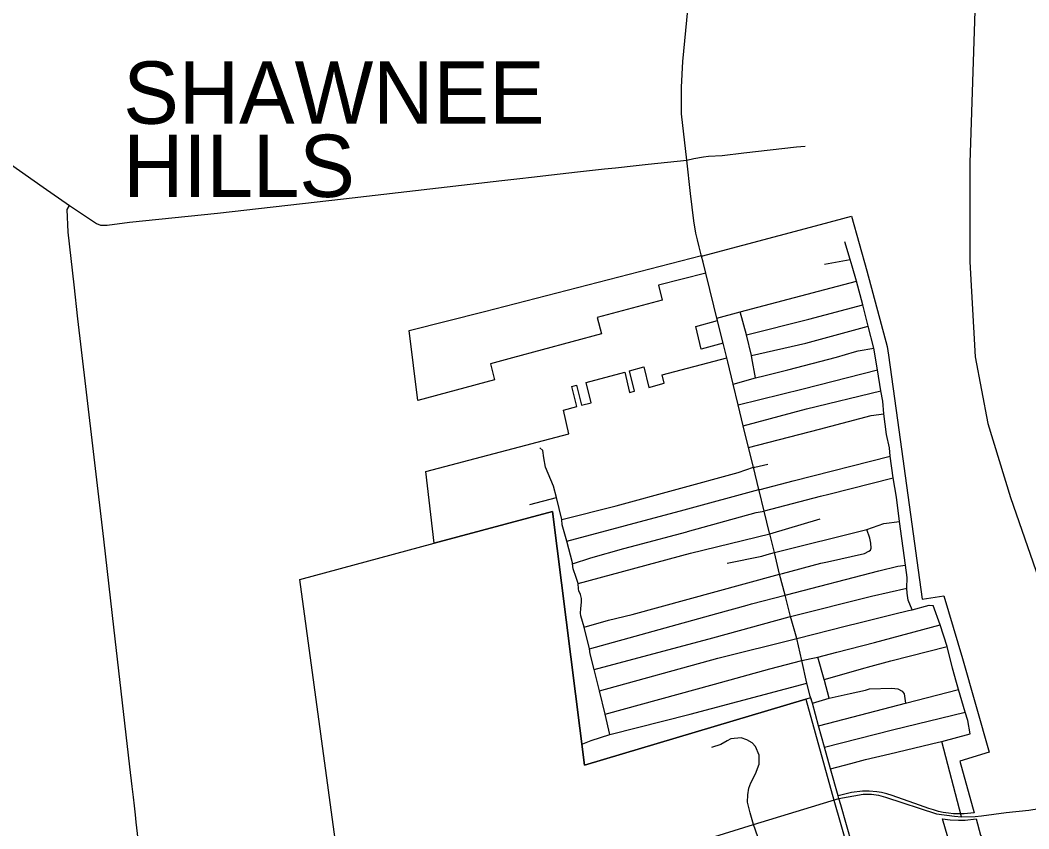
# Model space of a CAD drawing. Extents: x 1729596 to 1925846, y 659247 to 911751.
# Drawn here: x 1785084 to 1793175, y 784970 to 791458 of the extents above; entities that cross this region are included whole.
import ezdxf

# ---------------------------------------------------------------- set-up
doc = ezdxf.new("R2010")
doc.units = 0
for name, color, linetype in [('GM_X_City_Street', 7, 'Continuous'), ('GM_X_Corporation', 7, 'Continuous'), ('GM_X_Corporation_Text', 7, 'Continuous'), ('GM_X_County_Road', 7, 'Continuous'), ('GM_X_State_Route', 7, 'Continuous'), ('GM_X_Township', 7, 'Continuous'), ('GM_X_Township_Road', 7, 'Continuous')]:
    doc.layers.add(name, color=color, linetype=linetype)

msp = doc.modelspace()

# ---------------------------------------------------------------- linework, layer by layer
at = {"layer": 'GM_X_City_Street'}
for points in [[(1791756.8, 789484.5), (1791740.9, 789538), (1791699.7, 789680.5)], [(1791535.6, 789499), (1791740.9, 789538)], [(1792238.8, 786727.6), (1792208.2, 786804.7), (1792200.3, 786859.2), (1792196.3, 786900.4), (1792199.2, 786985.8), (1792186.1, 787084.3), (1792137.2, 787434.5), (1792115, 787631.9), (1792086.9, 787787), (1792064, 787958.8), (1792057.7, 788025.6), (1792034.4, 788134.4), (1792012.1, 788299.1), (1792004.5, 788400.2), (1791987.7, 788482.9), (1791960.1, 788652.9), (1791931.9, 788826.6), (1791886.3, 789002.5), (1791844.8, 789173.7), (1791792.5, 789364.8), (1791756.8, 789484.5)], [(1790672.6, 789065.9), (1790860.7, 789117.8), (1791538.4, 789298.1), (1791792.5, 789364.8)], [(1790909.4, 788932.1), (1791410.5, 789060.1), (1791844.8, 789173.7)], [(1790954.1, 788748.5), (1790950.8, 788766.3), (1790909.4, 788932.1), (1790860.7, 789117.8)], [(1790950.8, 788766.3), (1791387, 788867.2), (1791886.3, 789002.5)], [(1791058.9, 788606.7), (1791242.8, 788652.7), (1791632.1, 788753.6), (1791776.2, 788795.7)], [(1791776.2, 788795.7), (1791805.2, 788804.1), (1791931.9, 788826.6)], [(1790983.3, 788587.8), (1790954.1, 788748.5)], [(1790802.9, 788538.5), (1790983.3, 788587.8), (1791058.9, 788606.7)], [(1790843.6, 788372.1), (1791366.1, 788501.2), (1791960.1, 788652.9)], [(1790885, 788204.3), (1791391.4, 788339.5), (1791987.7, 788482.9)], [(1790925.9, 788030.4), (1791495.7, 788175.3), (1791909.5, 788286.7), (1792012.1, 788299.1)], [(1789560.2, 786938.6), (1789543.1, 786987.4), (1789519.6, 787054.9), (1789515, 787097.1), (1789514.1, 787104.5), (1789468.7, 787276.8), (1789432.9, 787407.6), (1789428.7, 787450.4), (1789386.4, 787627.6), (1789363.3, 787719.8), (1789298, 787872.3), (1789285.5, 787945.4), (1789277.7, 788006.1), (1789252.7, 788027)], [(1791283.7, 787760.7), (1792064, 787958.8)], [(1790976.5, 787872.7), (1791080.7, 787896.7)], [(1789428.7, 787450.4), (1789864, 787561.5), (1790843.1, 787829.9), (1790965.8, 787870.2), (1790976.5, 787872.7)], [(1789468.7, 787276.8), (1790409.8, 787529.5), (1791010, 787691.1), (1791018.8, 787693.4), (1791283.7, 787760.7)], [(1791570.7, 787655.7), (1792086.9, 787787)], [(1791055.4, 787520.8), (1791502.9, 787638.5), (1791570.7, 787655.7)], [(1789173.6, 787571), (1789386.4, 787627.6)], [(1790438.1, 787355.8), (1790988.5, 787507.7), (1791051, 787519.6), (1791055.4, 787520.8)], [(1791077, 787170.1), (1791134.7, 787187.2), (1791876.6, 787372.2), (1792011.5, 787418.6), (1792137.2, 787434.5)], [(1791096.4, 787335.2), (1791096.7, 787335.3), (1791501.9, 787456.1)], [(1789560.5, 786937.8), (1790461.8, 787182.4), (1791096.4, 787335.2)], [(1790026.7, 787244.7), (1790430.5, 787353.7), (1790438.1, 787355.8)], [(1791558.9, 787112.1), (1791856.3, 787179.8), (1791891, 787197.1), (1791904.1, 787205.8), (1791909.8, 787220.3), (1791908.4, 787260.8), (1791899.7, 787302.8), (1791876.6, 787372.2)], [(1789515, 787097.1), (1789661.5, 787143.1), (1789927.4, 787217.9), (1790026.7, 787244.7)], [(1790756.2, 787101), (1791033.9, 787157.3), (1791077, 787170.1)], [(1791198.5, 787019), (1791506.3, 787100.2), (1791558.9, 787112.1)], [(1791972.7, 787039), (1792124.3, 787078.1), (1792186.1, 787084.3)], [(1790890.7, 786935.1), (1791176.3, 787013.2), (1791198.5, 787019)], [(1791231.6, 786848.1), (1791972.7, 787039)], [(1789814.6, 785727.2), (1789776.7, 785890.5), (1789731.8, 786076.2), (1789688, 786247.4), (1789655.1, 786372.6), (1789650, 786414.7), (1789607.8, 786587.5), (1789581.8, 786677.6), (1789580, 786699), (1789581.8, 786737.1), (1789586.4, 786789.1), (1789585.5, 786818.9), (1789579, 786848.6), (1789564.2, 786878.4), (1789561.4, 786895.1), (1789560.5, 786937.8), (1789560.2, 786938.6)], [(1789607.8, 786587.5), (1789803.8, 786643.2), (1789992.5, 786689.7), (1790890.7, 786935.1)], [(1790914.5, 786764.5), (1790951.8, 786774.9), (1791219.3, 786844.9), (1791231.6, 786848.1)], [(1791251.7, 786671.2), (1791263.5, 786674.5), (1791912.6, 786835.3), (1792196.3, 786900.4)], [(1789650, 786414.7), (1790671.8, 786697.3), (1790914.5, 786764.5)], [(1792208.9, 786720.5), (1792238.8, 786727.6), (1792376.8, 786765), (1792407.7, 786762)], [(1792703.4, 785732.4), (1792685.6, 785839.5), (1792663.9, 785905.8), (1792611.5, 786086.7), (1792594.2, 786142.9), (1792562.6, 786258.1), (1792519.4, 786432.4), (1792463.7, 786605.8), (1792407.7, 786762)], [(1789688, 786247.4), (1790639.5, 786503.4), (1791251.7, 786671.2)], [(1791711.9, 786597.5), (1791812.3, 786622.6), (1792088.6, 786691.8), (1792208.9, 786720.5)], [(1791314.7, 786497.9), (1791711.9, 786597.5)], [(1791636.4, 786387.2), (1791937.8, 786465.5), (1792463.7, 786605.8)], [(1789731.8, 786076.2), (1790680.8, 786338.7), (1791314, 786497.7), (1791314.7, 786497.9)], [(1791861.1, 786260.9), (1791881.7, 786266.7), (1792067.4, 786318.6), (1792519.4, 786432.4)], [(1790653.3, 786131.6), (1791098.5, 786254), (1791353.4, 786320), (1791428.8, 786336)], [(1791428.8, 786336), (1791483.4, 786347.5), (1791636.4, 786387.2)], [(1791536, 786159.7), (1791533.8, 786168.2), (1791483.4, 786347.5)], [(1791533.8, 786168.2), (1791861.1, 786260.9)], [(1789597.7, 785651.6), (1789663.3, 785677.5), (1789814.6, 785727.2), (1790457.3, 785888.5), (1791393.4, 786137.9)], [(1789776.7, 785890.5), (1790653.3, 786131.6)], [(1791438.6, 785977.7), (1791572.7, 786018.1), (1791743, 786055.8), (1791864.5, 786081), (1791898, 786092.2), (1792076.6, 786097.7), (1792125.5, 786093.6), (1792159, 786075.4), (1792174.4, 786051.6), (1792185.6, 785979)], [(1791572.7, 786018.1), (1791536, 786159.7)], [(1791487, 785795), (1791765.3, 785867.3), (1792185.6, 785979), (1792611.5, 786086.7)], [(1791537, 785624.5), (1792082.4, 785763), (1792663.9, 785905.8)], [(1791085, 784728.5), (1791036.1, 784805.7), (1790967.3, 785004.9), (1790940.8, 785096.7), (1790917.7, 785184.3), (1790920.2, 785243.5), (1790927.9, 785295), (1790946, 785338.8), (1790982.7, 785411.7), (1791011.9, 785487.9), (1791011.9, 785561.1), (1790982.7, 785631.5), (1790956.3, 785660.8), (1790912.4, 785684.2), (1790868.4, 785698.8), (1790783.5, 785693), (1790754.2, 785675.4), (1790704.5, 785646.1), (1790628.3, 785622.7)], [(1792450.3, 785664.4), (1792477.4, 785670.9), (1792703.4, 785732.4)], [(1791585.4, 785450.2), (1791747.7, 785492.8), (1791865.8, 785527), (1792060.9, 785570.4), (1792450.3, 785664.4)], [(1792634.5, 785066.5), (1792477.4, 785670.9)], [(1786110.8, 783497.2), (1786160.6, 783512.9), (1786228.9, 783545.4), (1786321.6, 783619.1), (1786378.1, 783661), (1786427.2, 783697.4), (1786487.3, 783730.3), (1786569.3, 783755.7), (1786938.6, 783864.5), (1787087, 783901.3), (1787342.2, 783978), (1787586.5, 784047.3), (1787860, 784130.6), (1788122.7, 784193.2), (1788314.4, 784188.2), (1788880.9, 784350.9), (1789511.3, 784554.3), (1790303.6, 784798.2), (1790967.3, 785004.9), (1791651.9, 785213)], [(1791651.9, 785213), (1791651.9, 785213), (1791846.1, 785246.9), (1791913.1, 785248.2), (1791969.8, 785240.5), (1792026.5, 785225), (1792433.6, 785090.9), (1792577.8, 785071.6), (1792634.5, 785066.5), (1792746.1, 785068.9), (1792796.6, 785074.6), (1792994.5, 785100.6), (1793175.3, 785120.7), (1793622.7, 785191.4), (1794111.6, 785268.7), (1794207.3, 785281.3), (1794252.4, 785275.9), (1794298.5, 785238.8), (1794363.5, 785172), (1794388.8, 785145.4)]]:
    msp.add_lwpolyline(points, dxfattribs=at)
at = {"layer": 'GM_X_Corporation'}
msp.add_lwpolyline([(1788338.2, 787836.1), (1789485.1, 788139), (1789441.8, 788328.9), (1789549.6, 788357.9), (1789509, 788519.6), (1789546, 788529.6), (1789588, 788368.2), (1789663.1, 788388.4), (1789625, 788551), (1789933.7, 788633.4), (1789973.1, 788471), (1790010.7, 788480.9), (1789972.2, 788645), (1790087.5, 788675.2), (1790127.5, 788511.5), (1790250.6, 788544.7), (1790234.1, 788611.6), (1790752, 788749.1), (1790722.9, 788865.1), (1790547.2, 788818.3), (1790502.8, 789000.9), (1790677.2, 789047.4), (1790648.1, 789166.5), (1790584.1, 789428.3), (1790204.3, 789331.7), (1790234.8, 789210.2), (1789713.6, 789072.4), (1789746, 788941.7), (1789031.9, 788748), (1788856.8, 788701.4), (1788889.4, 788571.4), (1788273.7, 788407.5), (1788203.5, 788966.9), (1788809.5, 789121.7), (1790549.8, 789569.1), (1790550.6, 789565.7), (1791504.7, 789818.5), (1791752.8, 789884.2), (1791875.7, 789446.6), (1792038.1, 788840.2), (1792049.2, 788770.3), (1792122, 788248.2), (1792318.8, 786813.4), (1792492.4, 786838.8), (1792643.4, 786337.2), (1792856.8, 785584.9), (1792621.7, 785511.7), (1792738.1, 785097.2), (1792656.6, 785090.5), (1792634.5, 785089.8), (1792616.1, 785089.2), (1792570, 785090.5), (1792530.2, 785094.3), (1792489.3, 785100.9), (1792450.2, 785109.9), (1792411.8, 785121.2), (1792374.1, 785133.2), (1792298.2, 785159.7), (1792078.1, 785237.7), (1792035.2, 785250.6), (1791994.4, 785260), (1791955.1, 785266.4), (1791895.4, 785271.9), (1791840.6, 785271.8), (1791752.2, 785261.5), (1791646.3, 785234.7), (1791585.4, 785450.2), (1791537, 785624.5), (1791487, 785795), (1791438.6, 785977.6), (1791425.4, 786021.1), (1791386.8, 786010.1), (1789612.1, 785481.6), (1789353, 787515.2), (1788405.7, 787262.9)], close=True, dxfattribs=at)
msp.add_lwpolyline([(1782400.8, 784262), (1786021.2, 784680.3), (1786052.5, 784438.6), (1787610.3, 784885.4), (1787327.7, 786971.4), (1788405.7, 787262.9), (1789353, 787515.2), (1789612.1, 785481.6), (1791386.8, 786010.1), (1791611.9, 785199.4), (1791785.8, 784594.5), (1791822.7, 784606.5), (1792459.4, 784811.9), (1792543.8, 784839.1), (1792483.1, 785050.9), (1792543.5, 785042.3), (1792610.3, 785038.7), (1792665.3, 785040.3), (1792751.8, 785048.6), (1792788.2, 784919.2), (1792848.3, 784828.5), (1793467.6, 783905.1)], dxfattribs=at)
at = {"layer": 'GM_X_County_Road'}
for points in [[(1784637.9, 790333.5), (1784843.3, 790356.7), (1784876.6, 790356.8), (1784894.3, 790354.6), (1784911.7, 790350.8), (1784928.7, 790345.4), (1784960.9, 790330.3), (1785005.7, 790303.2), (1785267.5, 790117.1), (1785478.8, 789971.9)], [(1785478.8, 789971.9), (1785695.1, 789825.6), (1785728.1, 789813.2), (1785781.6, 789813.2), (1785960.9, 789838), (1786665.4, 789910.1), (1787678.6, 790024.5), (1788948.6, 790172), (1789067.8, 790185.5), (1789208.7, 790202), (1789277.1, 790209.3), (1789555.4, 790241.6), (1789772.6, 790264.8), (1789859.7, 790273.7), (1790024.6, 790292.6), (1790121, 790303), (1790431.8, 790335.3)]]:
    msp.add_lwpolyline(points, dxfattribs=at)
at = {"layer": 'GM_X_State_Route'}
for points in [[(1790431.8, 790335.3), (1790390.2, 790705.8), (1790390.2, 790919.6), (1790398.9, 791127.5), (1790495.5, 792123.3), (1790513.6, 792320.2), (1790520, 792424), (1790520.9, 792501.2), (1790515.8, 792584.3), (1790506.6, 792651.8), (1790486.6, 792747.6), (1790461.5, 792837.7), (1790398.6, 793056.3), (1790334, 793268), (1790306.9, 793367.3)], [(1790550.6, 789565.7), (1790530.2, 789639.9), (1790517.2, 789695.6), (1790504.1, 789749.9), (1790487.2, 789846.7), (1790462.5, 790066.5), (1790431.8, 790335.3)], [(1790562.8, 789515.8), (1790550.6, 789565.7)], [(1790587.1, 789416), (1790584.1, 789428.3), (1790562.8, 789515.8)], [(1790677.6, 789045.8), (1790677.2, 789047.4), (1790672.6, 789065.9), (1790648.1, 789166.5), (1790587.1, 789416)], [(1790722.9, 788865.1), (1790677.6, 789045.8)], [(1790759.9, 788716.4), (1790752, 788749.1), (1790722.9, 788865.1)], [(1791422.4, 786035.2), (1791393.4, 786137.9), (1791353.4, 786320), (1791314, 786497.7), (1791263.5, 786674.5), (1791219.3, 786844.9), (1791176.3, 787013.2), (1791134.7, 787187.2), (1791096.7, 787335.3), (1791095.3, 787340.7), (1791051, 787519.6), (1791011.5, 787684.8), (1791010, 787691.1), (1790965.8, 787870.2), (1790925.9, 788030.4), (1790885, 788204.3), (1790843.6, 788372.1), (1790802.9, 788538.5), (1790759.9, 788716.4)], [(1791651.9, 785213), (1791646.4, 785234.7), (1791585.4, 785450.2), (1791537, 785624.5), (1791487, 785795), (1791438.6, 785977.7), (1791422.4, 786035.2)], [(1791666.1, 785162.9), (1791651.9, 785213)], [(1791821.3, 784611.5), (1791757.4, 784842.4), (1791666.1, 785162.9)]]:
    msp.add_lwpolyline(points, dxfattribs=at)
at = {"layer": 'GM_X_Township'}
msp.add_lwpolyline([(1793566.2, 795093.7), (1792419.4, 795164.6), (1792575.9, 794355.5), (1792720.5, 793710.5), (1792763.7, 793045.1), (1792782.7, 792752.7), (1792702.3, 790313.3), (1792702.4, 789519.4), (1792744.6, 788755.4), (1792845.1, 788222), (1793027.9, 787628.5), (1793570.2, 786064.3)], dxfattribs=at)
at = {"layer": 'GM_X_Township_Road'}
for points in [[(1790431.8, 790335.3), (1790487.9, 790347.7), (1790565.5, 790361), (1790604.7, 790367), (1790715.3, 790372.4), (1790889.2, 790392.2), (1791311.7, 790442.2), (1791379.9, 790447.1)], [(1786081.4, 784452.9), (1786079.1, 784473.7), (1786015.3, 785023.9), (1786008.5, 785081.3), (1786001.8, 785154), (1785992.2, 785223), (1785983.4, 785308.6), (1785963.6, 785466.2), (1785835.9, 786586.8), (1785811.7, 786799), (1785754.3, 787294.9), (1785610.6, 788517.6), (1785547.6, 789062.7), (1785517.1, 789335), (1785468.5, 789757.6), (1785460.3, 789939), (1785478.8, 789971.9)]]:
    msp.add_lwpolyline(points, dxfattribs=at)

# ---------------------------------------------------------------- texts
at = {"layer": 'GM_X_Corporation_Text'}
for s, p in [('SHAWNEE', (1785910.5, 790626.6)), ('HILLS', (1785910.5, 790039))]:
    msp.add_text(s, height=500, rotation=0.00001, dxfattribs=at).set_placement(p)

doc.saveas('drawing.dxf')
